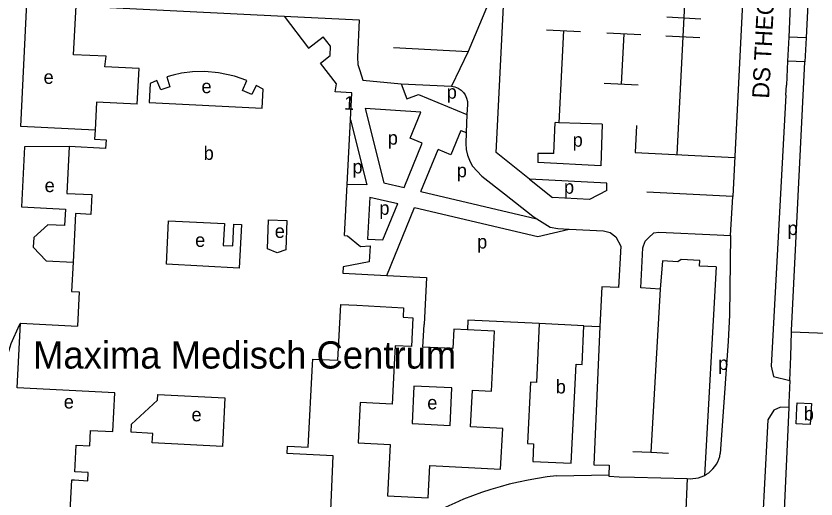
# Model space of a CAD drawing. Extents: x 161773 to 163836, y 384796 to 386521.
# Drawn here: x 161899.9 to 162134.8, y 384960.5 to 385102.4 of the extents above; entities that cross this region are included whole.
import ezdxf

# ---------------------------------------------------------------- set-up
doc = ezdxf.new("R2010")
doc.units = 0
for name, color, linetype in [('BLT_Basislijn', 7, 'Continuous'), ('BLT_Bebouwing', 7, 'Continuous'), ('BLT_Bebouwing_beschrifting', 7, 'Continuous'), ('BLT_Centroide', 7, 'Continuous'), ('BLT_Huisnummer', 7, 'Continuous'), ('BLT_Straatnaam', 7, 'Continuous'), ('BLT_Vlakafsluiter', 7, 'Continuous')]:
    doc.layers.add(name, color=color, linetype=linetype)

msp = doc.modelspace()

# ---------------------------------------------------------------- linework, layer by layer
at = {"layer": 'BLT_Basislijn'}
for p, q in [((162143.85, 385324.21), (162131.95, 385096.02)), ((162136.64, 385303.95), (162126.81, 385096.24)), ((162100.51, 385193.25), (162094.01, 385061.7)), ((162091, 385102.14), (162100.99, 385101.63)), ((162055.74, 385098.38), (162065.73, 385097.87)), ((162060.7, 385098.12), (162059.37, 385071.07)), ((162073.41, 385097.48), (162083.4, 385096.97)), ((162078.39, 385097.22), (162077.66, 385082.4)), ((162090.73, 385096.6), (162100.72, 385096.09)), ((162126.81, 385096.24), (162126.47, 385089.13)), ((162131.95, 385096.02), (162126.81, 385096.24)), ((162131.95, 385096.02), (162131.54, 385088.97)), ((162010.77, 385093.15), (162032.75, 385092.01)), ((162126.47, 385089.13), (162126.14, 385082.11)), ((162131.54, 385088.97), (162126.47, 385089.13)), ((162013.04, 385082.51), (162027.78, 385081.76)), ((162072.66, 385082.66), (162082.64, 385082.15)), ((162126, 385079.17), (162126.14, 385082.11)), ((162018.79, 385074.16), (162002.51, 385075.19)), ((162057.81, 385062.05), (162058.22, 385071.12)), ((162059.37, 385071.07), (162058.22, 385071.12)), ((162072.06, 385070.6), (162059.37, 385071.07)), ((162072.06, 385070.6), (162071.61, 385058.36)), ((162082.08, 385070.23), (162081.69, 385062.33)), ((162013.92, 385051.99), (162019.22, 385065.07)), ((162018.85, 385050.83), (162023.85, 385063.17)), ((162057.81, 385062.05), (162053.15, 385062.05)), ((162053.15, 385062.05), (162053.15, 385059.34)), ((162081.69, 385062.33), (162110.95, 385060.84)), ((162071.61, 385058.36), (162053.15, 385059.34)), ((162002.96, 385052.82), (161997.2, 385052.95)), ((162073.37, 385053.26), (162050.74, 385054.46)), ((162050.74, 385054.46), (162057.47, 385049.1)), ((162073.37, 385051.17), (162073.37, 385053.26)), ((162109.7, 385037.94), (162110.38, 385049.38)), ((162007.69, 385036.62), (162012.02, 385047.3)), ((162008.85, 385026.15), (162016.95, 385046.14)), ((162105.86, 385038.12), (162109.7, 385037.94)), ((162105.53, 385028.73), (162102.07, 384967.42)), ((162089.05, 385022.19), (162083.39, 385022.55)), ((162089.05, 385022.19), (162086.3, 384974.21)), ((162109.42, 385014.48), (162109.02, 385006.83)), ((162066.7, 385011.4), (162071.41, 385011.17)), ((162127.4, 385002.4), (162127.63, 385009.65)), ((162127.63, 385009.65), (162272.59, 385003.94)), ((162127.18, 384995.27), (162127.4, 385002.4)), ((162127.18, 384995.27), (162126.9, 384988.87)), ((162126.9, 384988.87), (162126.84, 384987.4)), ((162126.84, 384987.4), (162122.36, 384890.59)), ((162081.06, 384974.46), (162086.3, 384974.21)), ((162086.3, 384974.21), (162091.55, 384973.96)), ((162074.15, 384970.41), (162074, 384967.54)), ((162058.68, 384967.29), (162074, 384967.54)), ((162077.07, 384967.03), (162081.56, 384966.93)), ((162081.56, 384966.93), (162097.01, 384966.49)), ((162097.01, 384966.49), (162096.45, 384954.25))]:
    msp.add_line(p, q, dxfattribs=at)
for points in [[(162040.93, 385062.28), (162049.05, 385224.92), (162118.83, 385221.44)], [(162118.83, 385221.44), (162117.5, 385192.72), (162113.15, 385104.33), (162110.38, 385049.38)], [(161923.17, 385068.89), (161901.33, 385069.99), (161903.08, 385106.19)], [(161978.65, 385102.34), (162000.72, 385101.28), (162000.21, 385090.28)], [(162000.21, 385090.28), (162000.32, 385088.21), (162000.86, 385086.36), (162001.82, 385083.57), (162013.04, 385082.51)], [(162127.63, 385009.65), (162127.64, 385009.99), (162131.54, 385088.97)], [(162013.04, 385082.51), (162014.69, 385078.11), (162018.11, 385079.36), (162032.36, 385073.47)], [(162027.78, 385081.76), (162028.83, 385081.56), (162029.78, 385081.18), (162030.63, 385080.62), (162031.32, 385079.95), (162031.82, 385079.23), (162032.23, 385078.3), (162032.46, 385077.3), (162032.49, 385076.39), (162032.36, 385073.47)], [(162126, 385079.17), (162121.65, 384999.49), (162122.36, 384996.48), (162127.18, 384995.27)], [(162002.51, 385075.19), (162007.97, 385053.38), (162013.92, 385051.99)], [(162019.22, 385065.07), (162015.67, 385066.54), (162018.79, 385074.16)], [(162032.36, 385073.47), (162032.14, 385068.15)], [(161998.17, 385071.94), (162002.96, 385052.82)], [(162030.55, 385068.81), (162027.61, 385061.62), (162023.85, 385063.17)], [(162030.55, 385068.81), (162032.14, 385068.15)], [(162032.14, 385068.15), (162032, 385064.91), (162032.1, 385063.23), (162032.49, 385061.53), (162033.28, 385059.52), (162034.01, 385058.26), (162036.73, 385055.32), (162043.34, 385050.14), (162051.71, 385043.57), (162052.85, 385042.85)], [(161915.52, 385064.04), (161902.42, 385063.98), (161901.52, 385046.33), (161914.47, 385045.67), (161914.23, 385040.84), (161909.3, 385041.09), (161905.15, 385037.28), (161905.01, 385034.49), (161908.76, 385030.44), (161916.69, 385030.03)], [(162050.74, 385054.46), (162040.93, 385062.28)], [(162018.85, 385050.83), (162052.85, 385042.85)], [(162073.37, 385051.17), (162068.29, 385048.5), (162057.47, 385049.1)], [(162110.38, 385049.38), (162085.2, 385050.6)], [(162003.82, 385049.22), (162003.17, 385036.87), (162007.69, 385036.62)], [(162003.82, 385049.22), (162012.02, 385047.3)], [(162016.95, 385046.14), (162053.18, 385037.63), (162062.36, 385039.79)], [(162052.85, 385042.85), (162056.76, 385040.34), (162059.03, 385039.96), (162062.36, 385039.79)], [(162062.36, 385039.79), (162072.4, 385039.29), (162074.44, 385038.78), (162076.1, 385037.55), (162077.51, 385034.81), (162076.87, 385022.6)], [(162083.39, 385022.55), (162083.96, 385034.25), (162084.7, 385036.23), (162085.69, 385037.27), (162087.19, 385038.71), (162088.72, 385038.89), (162105.86, 385038.12)], [(162109.7, 385037.94), (162109.42, 385014.48)], [(162105.53, 385028.73), (162100.63, 385028.93), (162100.7, 385030.61), (162095.22, 385030.83), (162094.28, 385030.2), (162089.74, 385030.48), (162089.05, 385022.19)], [(162076.87, 385022.6), (162071.91, 385022.81), (162071.41, 385011.17)], [(162053.59, 385012.03), (162032.64, 385013.04), (162032.49, 385010.18)], [(161901.22, 385012.12), (161900.86, 385011.6), (161898.39, 385006.11), (161896.34, 384999.22), (161894.34, 384986.25), (161894.49, 384982.12), (161897.13, 384949.44), (161897.27, 384944.89), (161897.04, 384935.87), (161897.37, 384931.09), (161898.71, 384923.27), (161900.44, 384916.67), (161901.61, 384913.87), (161902.51, 384914.77), (161903.09, 384925.99), (161911.95, 384925.55)], [(162071.41, 385011.17), (162069.64, 384970.56), (162074.15, 384970.41)], [(162109.02, 385006.83), (162107.26, 384982.01), (162106.74, 384973.85)], [(162126.84, 384987.4), (162124.39, 384987.51), (162122.48, 384986.63), (162120.73, 384983.77), (162118.27, 384936.88)], [(162102.07, 384967.42), (162102.65, 384967.73), (162103.34, 384968.21), (162103.99, 384968.74), (162104.58, 384969.34), (162105.11, 384969.99), (162105.58, 384970.68), (162105.98, 384971.42), (162106.31, 384972.2), (162106.56, 384973), (162106.74, 384973.85)], [(162058.68, 384967.29), (162055.88, 384966.95), (162053.08, 384966.53), (162050.3, 384966.04), (162047.53, 384965.46), (162044.78, 384964.8), (162042.05, 384964.07), (162039.34, 384963.27), (162036.65, 384962.38), (162033.99, 384961.42), (162031.36, 384960.39), (162028.76, 384959.28), (162026.19, 384958.09), (162023.66, 384956.84), (162021.16, 384955.51), (162018.7, 384954.12), (162016.28, 384952.65), (162013.9, 384951.12)], [(162074, 384967.54), (162074.01, 384967.23), (162077.07, 384967.03)], [(162097.01, 384966.49), (162097.85, 384966.43), (162098.69, 384966.46), (162099.52, 384966.56), (162100.34, 384966.74), (162101.14, 384967), (162101.91, 384967.33), (162102.07, 384967.42)]]:
    msp.add_lwpolyline(points, dxfattribs=at)
at = {"layer": 'BLT_Bebouwing'}
for p, q in [((161923.17, 385068.89), (161923.03, 385066.26)), ((161917.43, 385044.35), (161916.69, 385030.03)), ((161900.27, 384993.15), (161901.22, 385012.12)), ((161901.22, 385012.12), (161917.99, 385011.26)), ((162050.96, 384994.82), (162050.12, 384976.75)), ((161928.93, 384991.69), (161900.27, 384993.15)), ((161928.36, 384980.31), (161928.93, 384991.69)), ((161961.29, 384990.21), (161960.58, 384975.91)), ((162129.24, 384987.29), (162129.31, 384988.76)), ((162129.31, 384988.76), (162133.46, 384988.55))]:
    msp.add_line(p, q, dxfattribs=at)
for points in [[(161935.54, 385076.52), (161936.08, 385086.96), (161926.03, 385087.46), (161926.44, 385090.58), (161916.87, 385091), (161917.59, 385105.41)], [(161917.59, 385105.41), (161978.65, 385102.34)], [(161978.65, 385102.34), (161985.82, 385092.94), (161990.12, 385096.3)], [(161998.57, 385079.87), (161993.69, 385080.11), (161994.03, 385082.47), (161989.33, 385088.58), (161992.22, 385090.86), (161992.3, 385093.58), (161990.12, 385096.3)], [(161998.17, 385071.94), (161998.57, 385079.87)], [(161935.54, 385076.52), (161923.54, 385077.06), (161923.17, 385068.89)], [(161997.2, 385052.95), (161998.17, 385071.94)], [(161915.52, 385064.04), (161914.85, 385050.3), (161922.24, 385049.93), (161921.94, 385044.12), (161917.43, 385044.35)], [(161923.03, 385066.26), (161926.41, 385066.06), (161926.25, 385063.51), (161915.52, 385064.04)], [(161996.44, 385037.9), (161997.2, 385052.95)], [(161944.09, 385029.47), (161944.76, 385042.27), (161961.12, 385041.41), (161960.78, 385035), (161963.59, 385034.85), (161963.93, 385041.27), (161966.18, 385041.15), (161965.51, 385028.34), (161944.09, 385029.47)], [(161974.07, 385042.49), (161979.43, 385042.33), (161979.17, 385033.68), (161976.58, 385032.82), (161973.82, 385034.04), (161974.07, 385042.49)], [(161996.44, 385037.9), (161997.28, 385037.85), (162001.08, 385034.7), (162003.97, 385034.86), (162003.68, 385030.21), (161995.97, 385028.69), (161995.87, 385026.83)], [(161916.69, 385030.03), (161916.25, 385021.43), (161918.46, 385021.31), (161917.99, 385011.26)], [(161995.87, 385026.83), (162008.85, 385026.15)], [(162008.85, 385026.15), (162020.47, 385025.54), (162019.78, 385011.79)], [(161992.29, 384954.85), (161993.03, 384973.17), (161981.31, 384973.78), (161979.55, 384973.89), (161979.66, 384976.04), (161985.74, 384975.72), (161987.02, 385000), (161987.1, 385001.61), (161994.46, 385001.23), (161995.32, 385017.65)], [(161995.32, 385017.65), (162000, 385017.4), (162013.75, 385016.68), (162013.61, 385013.92), (162016.47, 385013.76), (162016.02, 385005.25), (162011.24, 385005.5), (162010.95, 385000), (162010.34, 384988.37), (162001, 384988.86), (162000.38, 384976.99), (162009.83, 384976.5), (162009.03, 384961.42), (162020.99, 384960.79), (162021.49, 384970.31), (162042.21, 384969.22), (162042.84, 384981.17), (162033.42, 384981.67), (162033.99, 384992.48), (162039.54, 384992.18), (162039.96, 385000), (162040.47, 385009.76), (162032.49, 385010.18)], [(162032.49, 385010.18), (162028.54, 385010.39), (162028.24, 385004.68), (162019.43, 385005.14), (162019.78, 385011.79)], [(162050.12, 384976.75), (162051.9, 384976.66), (162051.67, 384971.5), (162062.98, 384970.96), (162064.38, 385000.07), (162066.15, 384999.98), (162066.7, 385011.4)], [(162053.59, 385012.03), (162052.75, 384994.73), (162050.96, 384994.82)], [(162066.7, 385011.4), (162053.59, 385012.03)], [(161933.74, 384980.07), (161933.87, 384982.49), (161941.48, 384989.55), (161941.56, 384991.18), (161961.29, 384990.21)], [(162130.87, 384982.47), (162129.01, 384982.56), (162129.24, 384987.29)], [(162133.46, 384988.55), (162133.15, 384982.36), (162130.87, 384982.47)], [(161917.13, 384966.06), (161921.04, 384965.86), (161921.17, 384968.3), (161917.25, 384968.5), (161917.65, 384976.28), (161921.59, 384976.08), (161921.83, 384980.61), (161928.36, 384980.31)], [(161960.58, 384975.91), (161939.96, 384977.01), (161940.11, 384979.73), (161933.74, 384980.07)], [(161911.95, 384925.55), (161913.38, 384953.36), (161915.69, 384953.24), (161916.35, 384966.1), (161917.13, 384966.06)]]:
    msp.add_lwpolyline(points, dxfattribs=at)
for points in [[(161939.07, 385076.98), (161972.21, 385075.37), (161972.51, 385080.92), (161970.46, 385082.04), (161969.17, 385079.37), (161966.48, 385080.57), (161967.73, 385083.47), (161964.13, 385084.76), (161959.39, 385085.71), (161955.42, 385086.1), (161951.78, 385086.06), (161948.51, 385085.66), (161946.07, 385085.07), (161944.24, 385084.57), (161945.13, 385081.64), (161942.46, 385080.71), (161941.34, 385083.49), (161939.31, 385082.54)], [(162016.77, 384993.66), (162016.28, 384982.68), (162027.4, 384982.09), (162027.92, 384993.11)]]:
    msp.add_lwpolyline(points, close=True, dxfattribs=at)
at = {"layer": 'BLT_Vlakafsluiter'}
for p, q in [((162038.05, 385104.84), (162032.75, 385092.01)), ((162032.75, 385092.01), (162027.78, 385081.76))]:
    msp.add_line(p, q, dxfattribs=at)

# ---------------------------------------------------------------- texts
at = {"layer": 'BLT_Bebouwing_beschrifting'}
msp.add_text('Maxima Medisch Centrum', height=8, dxfattribs=at).set_placement((161904.95, 384998.81))
at = {"layer": 'BLT_Centroide'}
for s, p in [('e', (161908.04, 385082.49)), ('e', (161954.4, 385079.74)), ('p', (162026.4, 385078.12)), ('p', (162009.1, 385064.61)), ('p', (162063.38, 385064.01)), ('b', (161955.04, 385060.14)), ('p', (161998.74, 385056.16)), ('p', (162029.36, 385055.03)), ('e', (161908.35, 385050.67)), ('p', (162060.83, 385050.19)), ('p', (162006.62, 385044)), ('p', (162126.48, 385038.05)), ('e', (161975.92, 385037.21)), ('e', (161952.54, 385034.57)), ('p', (162035.33, 385034.09)), ('p', (162106.11, 384998.39)), ('b', (162058.41, 384991.48)), ('e', (161913.97, 384987.07)), ('e', (162020.69, 384986.8)), ('b', (162131.23, 384983.56)), ('e', (161951.48, 384983.3))]:
    msp.add_text(s, height=4, dxfattribs=at).set_placement(p)
at = {"layer": 'BLT_Huisnummer'}
msp.add_text('1', height=4, rotation=356.987, dxfattribs=at).set_placement((161996.2, 385074.94))
at = {"layer": 'BLT_Straatnaam'}
msp.add_text('DS THEODOR FLIEDNERSTRAAT', height=5, rotation=87.0091, dxfattribs=at).set_placement((162121.04, 385078.07))

doc.saveas('drawing.dxf')
